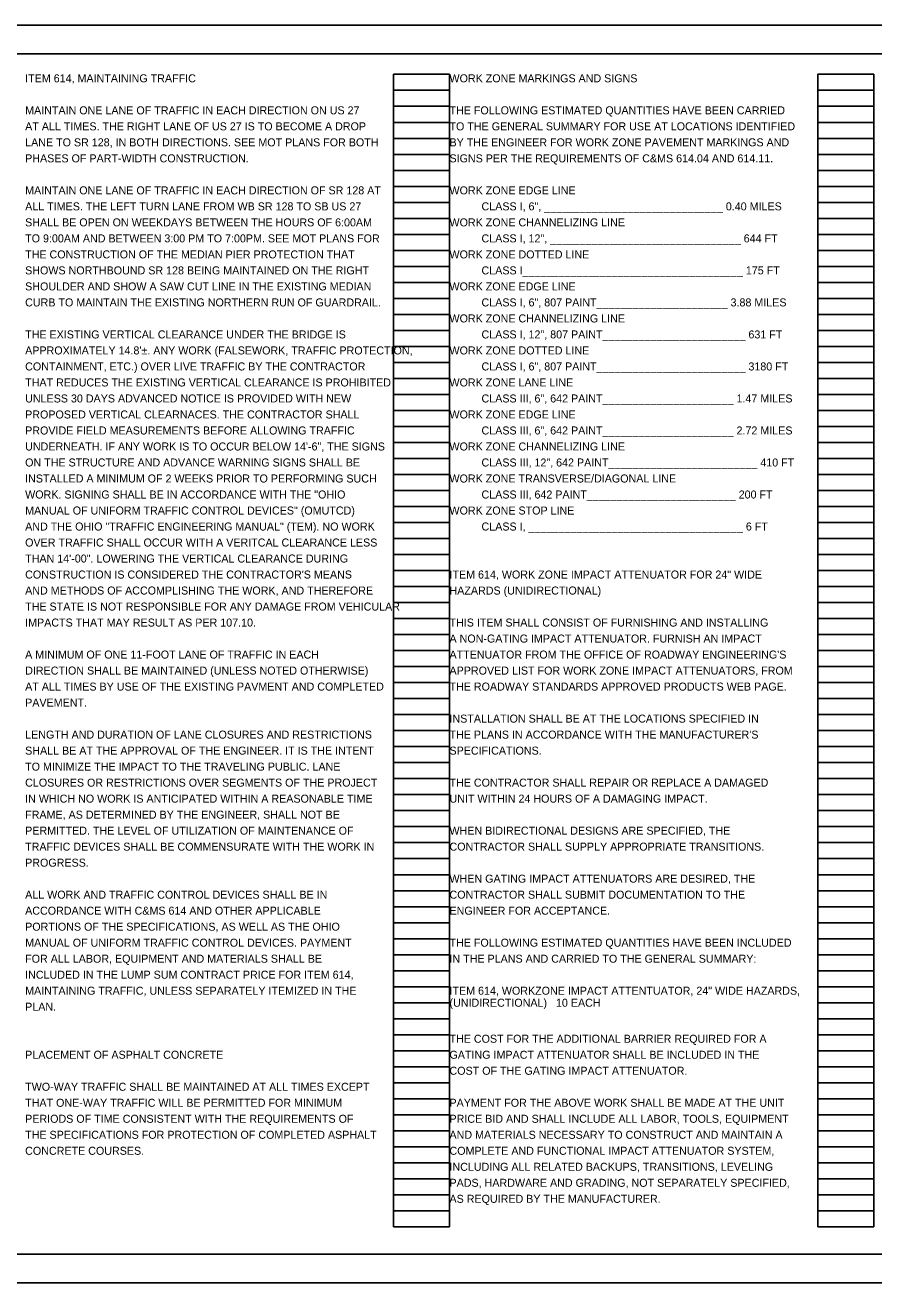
# Model space of a CAD drawing. Extents: x -7.1 to 46.9, y -17.8 to 23.9.
# Drawn here: x 2.4 to 17.24, y 0 to 22 of the extents above; entities that cross this region are included whole.
import ezdxf

# ---------------------------------------------------------------- set-up
doc = ezdxf.new("R2010")
doc.units = 0
for name, color, linetype in [('SH_Border', 7, 'Continuous'), ('SH_Cut_Line', 7, 'Continuous'), ('SH_Data', 7, 'Continuous'), ('SH_Text', 7, 'Continuous')]:
    doc.layers.add(name, color=color, linetype=linetype)

msp = doc.modelspace()

# ---------------------------------------------------------------- linework, layer by layer
at = {"layer": 'SH_Border'}
msp.add_lwpolyline([(1.5, 21.5), (33.5, 21.5), (33.5, 0.5), (1.5, 0.5)], close=True, dxfattribs=at)
at = {"layer": 'SH_Cut_Line'}
msp.add_lwpolyline([(0, 0), (34, 0), (34, 22), (0, 22)], close=True, dxfattribs=at)
at = {"layer": 'SH_Data'}
for p, q in [((8.84, 0.98), (8.84, 21.14)), ((8.84, 21.14), (9.82, 21.14)), ((9.82, 0.98), (9.82, 21.14)), ((16.26, 0.98), (16.26, 21.14)), ((16.26, 21.14), (17.24, 21.14)), ((17.24, 0.98), (17.24, 21.14)), ((8.84, 20.86), (9.82, 20.86)), ((16.26, 20.86), (17.24, 20.86)), ((8.84, 20.58), (9.82, 20.58)), ((16.26, 20.58), (17.24, 20.58)), ((8.84, 20.3), (9.82, 20.3)), ((16.26, 20.3), (17.24, 20.3)), ((8.84, 20.02), (9.82, 20.02)), ((16.26, 20.02), (17.24, 20.02)), ((8.84, 19.74), (9.82, 19.74)), ((16.26, 19.74), (17.24, 19.74)), ((8.84, 19.46), (9.82, 19.46)), ((16.26, 19.46), (17.24, 19.46)), ((8.84, 19.18), (9.82, 19.18)), ((16.26, 19.18), (17.24, 19.18)), ((8.84, 18.9), (9.82, 18.9)), ((16.26, 18.9), (17.24, 18.9)), ((8.84, 18.62), (9.82, 18.62)), ((16.26, 18.62), (17.24, 18.62)), ((8.84, 18.34), (9.82, 18.34)), ((16.26, 18.34), (17.24, 18.34)), ((8.84, 18.06), (9.82, 18.06)), ((16.26, 18.06), (17.24, 18.06)), ((8.84, 17.78), (9.82, 17.78)), ((16.26, 17.78), (17.24, 17.78)), ((8.84, 17.5), (9.82, 17.5)), ((16.26, 17.5), (17.24, 17.5)), ((8.84, 17.22), (9.82, 17.22)), ((16.26, 17.22), (17.24, 17.22)), ((8.84, 16.94), (9.82, 16.94)), ((16.26, 16.94), (17.24, 16.94)), ((8.84, 16.66), (9.82, 16.66)), ((16.26, 16.66), (17.24, 16.66)), ((8.84, 16.38), (9.82, 16.38)), ((16.26, 16.38), (17.24, 16.38)), ((8.84, 16.1), (9.82, 16.1)), ((16.26, 16.1), (17.24, 16.1)), ((8.84, 15.82), (9.82, 15.82)), ((16.26, 15.82), (17.24, 15.82)), ((8.84, 15.54), (9.82, 15.54)), ((16.26, 15.54), (17.24, 15.54)), ((8.84, 15.26), (9.82, 15.26)), ((16.26, 15.26), (17.24, 15.26)), ((8.84, 14.98), (9.82, 14.98)), ((16.26, 14.98), (17.24, 14.98)), ((8.84, 14.7), (9.82, 14.7)), ((16.26, 14.7), (17.24, 14.7)), ((8.84, 14.42), (9.82, 14.42)), ((16.26, 14.42), (17.24, 14.42)), ((8.84, 14.14), (9.82, 14.14)), ((16.26, 14.14), (17.24, 14.14)), ((8.84, 13.86), (9.82, 13.86)), ((16.26, 13.86), (17.24, 13.86)), ((8.84, 13.58), (9.82, 13.58)), ((16.26, 13.58), (17.24, 13.58)), ((8.84, 13.3), (9.82, 13.3)), ((16.26, 13.3), (17.24, 13.3)), ((8.84, 13.02), (9.82, 13.02)), ((16.26, 13.02), (17.24, 13.02)), ((8.84, 12.74), (9.82, 12.74)), ((16.26, 12.74), (17.24, 12.74)), ((8.84, 12.46), (9.82, 12.46)), ((16.26, 12.46), (17.24, 12.46)), ((8.84, 12.18), (9.82, 12.18)), ((16.26, 12.18), (17.24, 12.18)), ((8.84, 11.9), (9.82, 11.9)), ((16.26, 11.9), (17.24, 11.9)), ((8.84, 11.62), (9.82, 11.62)), ((16.26, 11.62), (17.24, 11.62)), ((8.84, 11.34), (9.82, 11.34)), ((16.26, 11.34), (17.24, 11.34)), ((8.84, 11.06), (9.82, 11.06)), ((16.26, 11.06), (17.24, 11.06)), ((8.84, 10.78), (9.82, 10.78)), ((16.26, 10.78), (17.24, 10.78)), ((8.84, 10.5), (9.82, 10.5)), ((16.26, 10.5), (17.24, 10.5)), ((8.84, 10.22), (9.82, 10.22)), ((16.26, 10.22), (17.24, 10.22)), ((8.84, 9.94), (9.82, 9.94)), ((16.26, 9.94), (17.24, 9.94)), ((8.84, 9.66), (9.82, 9.66)), ((16.26, 9.66), (17.24, 9.66)), ((8.84, 9.38), (9.82, 9.38)), ((16.26, 9.38), (17.24, 9.38)), ((8.84, 9.1), (9.82, 9.1)), ((16.26, 9.1), (17.24, 9.1)), ((8.84, 8.82), (9.82, 8.82)), ((16.26, 8.82), (17.24, 8.82)), ((8.84, 8.54), (9.82, 8.54)), ((16.26, 8.54), (17.24, 8.54)), ((8.84, 8.26), (9.82, 8.26)), ((16.26, 8.26), (17.24, 8.26)), ((8.84, 7.98), (9.82, 7.98)), ((16.26, 7.98), (17.24, 7.98)), ((8.84, 7.7), (9.82, 7.7)), ((16.26, 7.7), (17.24, 7.7)), ((8.84, 7.42), (9.82, 7.42)), ((16.26, 7.42), (17.24, 7.42)), ((8.84, 7.14), (9.82, 7.14)), ((16.26, 7.14), (17.24, 7.14)), ((8.84, 6.86), (9.82, 6.86)), ((16.26, 6.86), (17.24, 6.86)), ((8.84, 6.58), (9.82, 6.58)), ((16.26, 6.58), (17.24, 6.58)), ((8.84, 6.3), (9.82, 6.3)), ((16.26, 6.3), (17.24, 6.3)), ((8.84, 6.02), (9.82, 6.02)), ((16.26, 6.02), (17.24, 6.02)), ((8.84, 5.74), (9.82, 5.74)), ((16.26, 5.74), (17.24, 5.74)), ((8.84, 5.46), (9.82, 5.46)), ((16.26, 5.46), (17.24, 5.46)), ((8.84, 5.18), (9.82, 5.18)), ((16.26, 5.18), (17.24, 5.18)), ((8.84, 4.9), (9.82, 4.9)), ((16.26, 4.9), (17.24, 4.9)), ((8.84, 4.62), (9.82, 4.62)), ((16.26, 4.62), (17.24, 4.62)), ((8.84, 4.34), (9.82, 4.34)), ((16.26, 4.34), (17.24, 4.34)), ((8.84, 4.06), (9.82, 4.06)), ((16.26, 4.06), (17.24, 4.06)), ((8.84, 3.78), (9.82, 3.78)), ((16.26, 3.78), (17.24, 3.78)), ((8.84, 3.5), (9.82, 3.5)), ((16.26, 3.5), (17.24, 3.5)), ((8.84, 3.22), (9.82, 3.22)), ((16.26, 3.22), (17.24, 3.22)), ((8.84, 2.94), (9.82, 2.94)), ((16.26, 2.94), (17.24, 2.94)), ((8.84, 2.66), (9.82, 2.66)), ((16.26, 2.66), (17.24, 2.66)), ((8.84, 2.38), (9.82, 2.38)), ((16.26, 2.38), (17.24, 2.38)), ((8.84, 2.1), (9.82, 2.1)), ((16.26, 2.1), (17.24, 2.1)), ((8.84, 1.82), (9.82, 1.82)), ((16.26, 1.82), (17.24, 1.82)), ((8.84, 1.54), (9.82, 1.54)), ((16.26, 1.54), (17.24, 1.54)), ((8.84, 1.26), (9.82, 1.26)), ((16.26, 1.26), (17.24, 1.26)), ((8.84, 0.98), (9.82, 0.98)), ((16.26, 0.98), (17.24, 0.98))]:
    msp.add_line(p, q, dxfattribs=at)

# ---------------------------------------------------------------- texts
at = {"layer": 'SH_Text'}
for s, p in [('ITEM 614, MAINTAINING TRAFFIC', (2.4, 21)), ('WORK ZONE MARKINGS AND SIGNS', (9.82, 21)), ('MAINTAIN ONE LANE OF TRAFFIC IN EACH DIRECTION ON US 27', (2.4, 20.44)), ('THE FOLLOWING ESTIMATED QUANTITIES HAVE BEEN CARRIED', (9.82, 20.44)), ('AT ALL TIMES. THE RIGHT LANE OF US 27 IS TO BECOME A DROP ', (2.4, 20.16)), ('TO THE GENERAL SUMMARY FOR USE AT LOCATIONS IDENTIFIED', (9.82, 20.16)), ('LANE TO SR 128, IN BOTH DIRECTIONS. SEE MOT PLANS FOR BOTH', (2.4, 19.88)), ('BY THE ENGINEER FOR WORK ZONE PAVEMENT MARKINGS AND', (9.82, 19.88)), ('PHASES OF PART-WIDTH CONSTRUCTION.', (2.4, 19.6)), ('SIGNS PER THE REQUIREMENTS OF C&MS 614.04 AND 614.11.', (9.82, 19.6)), ('MAINTAIN ONE LANE OF TRAFFIC IN EACH DIRECTION OF SR 128 AT', (2.4, 19.04)), ('WORK ZONE EDGE LINE', (9.82, 19.04)), ('ALL TIMES. THE LEFT TURN LANE FROM WB SR 128 TO SB US 27', (2.4, 18.76)), ('CLASS I, 6", ______________________________ 0.40 MILES', (10.38, 18.76)), ('SHALL BE OPEN ON WEEKDAYS BETWEEN THE HOURS OF 6:00AM', (2.4, 18.48)), ('WORK ZONE CHANNELIZING LINE', (9.82, 18.48)), ('TO 9:00AM AND BETWEEN 3:00 PM TO 7:00PM. SEE MOT PLANS FOR', (2.4, 18.2)), ('CLASS I, 12", ________________________________ 644 FT', (10.38, 18.2)), ('THE CONSTRUCTION OF THE MEDIAN PIER PROTECTION THAT ', (2.4, 17.92)), ('WORK ZONE DOTTED LINE', (9.82, 17.92)), ('SHOWS NORTHBOUND SR 128 BEING MAINTAINED ON THE RIGHT', (2.4, 17.64)), ('CLASS I_____________________________________ 175 FT', (10.38, 17.64)), ('SHOULDER AND SHOW A SAW CUT LINE IN THE EXISTING MEDIAN', (2.4, 17.36)), ('WORK ZONE EDGE LINE', (9.82, 17.36)), ('CURB TO MAINTAIN THE EXISTING NORTHERN RUN OF GUARDRAIL.', (2.4, 17.08)), ('CLASS I, 6", 807 PAINT______________________ 3.88 MILES', (10.38, 17.08)), ('WORK ZONE CHANNELIZING LINE', (9.82, 16.8)), ('THE EXISTING VERTICAL CLEARANCE UNDER THE BRIDGE IS', (2.4, 16.52)), ('CLASS I, 12", 807 PAINT________________________ 631 FT', (10.38, 16.52)), ("APPROXIMATELY 14.8'±. ANY WORK (FALSEWORK, TRAFFIC PROTECTION,", (2.4, 16.24)), ('WORK ZONE DOTTED LINE', (9.82, 16.24)), ('CONTAINMENT, ETC.) OVER LIVE TRAFFIC BY THE CONTRACTOR', (2.4, 15.96)), ('CLASS I, 6", 807 PAINT_________________________ 3180 FT', (10.38, 15.96)), ('THAT REDUCES THE EXISTING VERTICAL CLEARANCE IS PROHIBITED', (2.4, 15.68)), ('WORK ZONE LANE LINE', (9.82, 15.68)), ('UNLESS 30 DAYS ADVANCED NOTICE IS PROVIDED WITH NEW', (2.4, 15.4)), ('CLASS III, 6", 642 PAINT______________________ 1.47 MILES', (10.38, 15.4)), ('PROPOSED VERTICAL CLEARNACES. THE CONTRACTOR SHALL ', (2.4, 15.12)), ('WORK ZONE EDGE LINE', (9.82, 15.12)), ('PROVIDE FIELD MEASUREMENTS BEFORE ALLOWING TRAFFIC', (2.4, 14.84)), ('CLASS III, 6", 642 PAINT______________________ 2.72 MILES', (10.38, 14.84)), ('UNDERNEATH. IF ANY WORK IS TO OCCUR BELOW 14\'-6", THE SIGNS', (2.4, 14.56)), ('WORK ZONE CHANNELIZING LINE', (9.82, 14.56)), ('ON THE STRUCTURE AND ADVANCE WARNING SIGNS SHALL BE', (2.4, 14.28)), ('CLASS III, 12", 642 PAINT_________________________ 410 FT', (10.38, 14.28)), ('INSTALLED A MINIMUM OF 2 WEEKS PRIOR TO PERFORMING SUCH', (2.4, 14)), ('WORK ZONE TRANSVERSE/DIAGONAL LINE', (9.82, 14)), ('WORK. SIGNING SHALL BE IN ACCORDANCE WITH THE "OHIO', (2.4, 13.72)), ('CLASS III, 642 PAINT_________________________ 200 FT', (10.38, 13.72)), ('MANUAL OF UNIFORM TRAFFIC CONTROL DEVICES" (OMUTCD)', (2.4, 13.44)), ('WORK ZONE STOP LINE', (9.82, 13.44)), ('AND THE OHIO "TRAFFIC ENGINEERING MANUAL" (TEM). NO WORK', (2.4, 13.16)), ('CLASS I, ____________________________________ 6 FT', (10.38, 13.16)), ('OVER TRAFFIC SHALL OCCUR WITH A VERITCAL CLEARANCE LESS', (2.4, 12.88)), ('THAN 14\'-00". LOWERING THE VERTICAL CLEARANCE DURING ', (2.4, 12.6)), ("CONSTRUCTION IS CONSIDERED THE CONTRACTOR'S MEANS ", (2.4, 12.32)), ('ITEM 614, WORK ZONE IMPACT ATTENUATOR FOR 24" WIDE', (9.82, 12.32)), ('AND METHODS OF ACCOMPLISHING THE WORK, AND THEREFORE', (2.4, 12.04)), ('HAZARDS (UNIDIRECTIONAL)', (9.82, 12.04)), ('THE STATE IS NOT RESPONSIBLE FOR ANY DAMAGE FROM VEHICULAR', (2.4, 11.76)), ('IMPACTS THAT MAY RESULT AS PER 107.10.', (2.4, 11.48)), ('THIS ITEM SHALL CONSIST OF FURNISHING AND INSTALLING', (9.82, 11.48)), ('A NON-GATING IMPACT ATTENUATOR. FURNISH AN IMPACT', (9.82, 11.2)), ('A MINIMUM OF ONE 11-FOOT LANE OF TRAFFIC IN EACH', (2.4, 10.92)), ("ATTENUATOR FROM THE OFFICE OF ROADWAY ENGINEERING'S", (9.82, 10.92)), ('DIRECTION SHALL BE MAINTAINED (UNLESS NOTED OTHERWISE)', (2.4, 10.64)), ('APPROVED LIST FOR WORK ZONE IMPACT ATTENUATORS, FROM', (9.82, 10.64)), ('AT ALL TIMES BY USE OF THE EXISTING PAVMENT AND COMPLETED', (2.4, 10.36)), ('THE ROADWAY STANDARDS APPROVED PRODUCTS WEB PAGE.', (9.82, 10.36)), ('PAVEMENT.', (2.4, 10.08)), ('INSTALLATION SHALL BE AT THE LOCATIONS SPECIFIED IN', (9.82, 9.8)), ('LENGTH AND DURATION OF LANE CLOSURES AND RESTRICTIONS', (2.4, 9.52)), ("THE PLANS IN ACCORDANCE WITH THE MANUFACTURER'S", (9.82, 9.52)), ('SHALL BE AT THE APPROVAL OF THE ENGINEER. IT IS THE INTENT', (2.4, 9.24)), ('SPECIFICATIONS.', (9.82, 9.24)), ('TO MINIMIZE THE IMPACT TO THE TRAVELING PUBLIC. LANE', (2.4, 8.96)), ('CLOSURES OR RESTRICTIONS OVER SEGMENTS OF THE PROJECT', (2.4, 8.68)), ('THE CONTRACTOR SHALL REPAIR OR REPLACE A DAMAGED', (9.82, 8.68)), ('IN WHICH NO WORK IS ANTICIPATED WITHIN A REASONABLE TIME', (2.4, 8.4)), ('UNIT WITHIN 24 HOURS OF A DAMAGING IMPACT.', (9.82, 8.4)), ('FRAME, AS DETERMINED BY THE ENGINEER, SHALL NOT BE', (2.4, 8.12)), ('PERMITTED. THE LEVEL OF UTILIZATION OF MAINTENANCE OF', (2.4, 7.84)), ('WHEN BIDIRECTIONAL DESIGNS ARE SPECIFIED, THE', (9.82, 7.84)), ('TRAFFIC DEVICES SHALL BE COMMENSURATE WITH THE WORK IN', (2.4, 7.56)), ('CONTRACTOR SHALL SUPPLY APPROPRIATE TRANSITIONS.', (9.82, 7.56)), ('PROGRESS.', (2.4, 7.28)), ('WHEN GATING IMPACT ATTENUATORS ARE DESIRED, THE', (9.82, 7)), ('ALL WORK AND TRAFFIC CONTROL DEVICES SHALL BE IN', (2.4, 6.72)), ('CONTRACTOR SHALL SUBMIT DOCUMENTATION TO THE', (9.82, 6.72)), ('ACCORDANCE WITH C&MS 614 AND OTHER APPLICABLE', (2.4, 6.44)), ('ENGINEER FOR ACCEPTANCE.', (9.82, 6.44)), ('PORTIONS OF THE SPECIFICATIONS, AS WELL AS THE OHIO', (2.4, 6.16)), ('MANUAL OF UNIFORM TRAFFIC CONTROL DEVICES. PAYMENT', (2.4, 5.88)), ('THE FOLLOWING ESTIMATED QUANTITIES HAVE BEEN INCLUDED', (9.82, 5.88)), ('FOR ALL LABOR, EQUIPMENT AND MATERIALS SHALL BE', (2.4, 5.6)), ('IN THE PLANS AND CARRIED TO THE GENERAL SUMMARY:', (9.82, 5.6)), ('INCLUDED IN THE LUMP SUM CONTRACT PRICE FOR ITEM 614,', (2.4, 5.32)), ('MAINTAINING TRAFFIC, UNLESS SEPARATELY ITEMIZED IN THE', (2.4, 5.04)), ('ITEM 614, WORKZONE IMPACT ATTENTUATOR, 24" WIDE HAZARDS,', (9.82, 5.04)), ('PLAN.', (2.4, 4.76)), ('(UNIDIRECTIONAL)   10 EACH', (9.82, 4.83)), ('THE COST FOR THE ADDITIONAL BARRIER REQUIRED FOR A', (9.82, 4.2)), ('PLACEMENT OF ASPHALT CONCRETE', (2.4, 3.92)), ('GATING IMPACT ATTENUATOR SHALL BE INCLUDED IN THE', (9.82, 3.92)), ('COST OF THE GATING IMPACT ATTENUATOR.', (9.82, 3.64)), ('TWO-WAY TRAFFIC SHALL BE MAINTAINED AT ALL TIMES EXCEPT', (2.4, 3.36)), ('THAT ONE-WAY TRAFFIC WILL BE PERMITTED FOR MINIMUM', (2.4, 3.08)), ('PAYMENT FOR THE ABOVE WORK SHALL BE MADE AT THE UNIT', (9.82, 3.08)), ('PERIODS OF TIME CONSISTENT WITH THE REQUIREMENTS OF', (2.4, 2.8)), ('PRICE BID AND SHALL INCLUDE ALL LABOR, TOOLS, EQUIPMENT', (9.82, 2.8)), ('THE SPECIFICATIONS FOR PROTECTION OF COMPLETED ASPHALT', (2.4, 2.52)), ('AND MATERIALS NECESSARY TO CONSTRUCT AND MAINTAIN A', (9.82, 2.52)), ('CONCRETE COURSES.', (2.4, 2.24)), ('COMPLETE AND FUNCTIONAL IMPACT ATTENUATOR SYSTEM,', (9.82, 2.24)), ('INCLUDING ALL RELATED BACKUPS, TRANSITIONS, LEVELING', (9.82, 1.96)), ('PADS, HARDWARE AND GRADING, NOT SEPARATELY SPECIFIED,', (9.82, 1.68)), ('AS REQUIRED BY THE MANUFACTURER.', (9.82, 1.4))]:
    msp.add_text(s, height=0.14, dxfattribs=at).set_placement(p)

doc.saveas('drawing.dxf')
